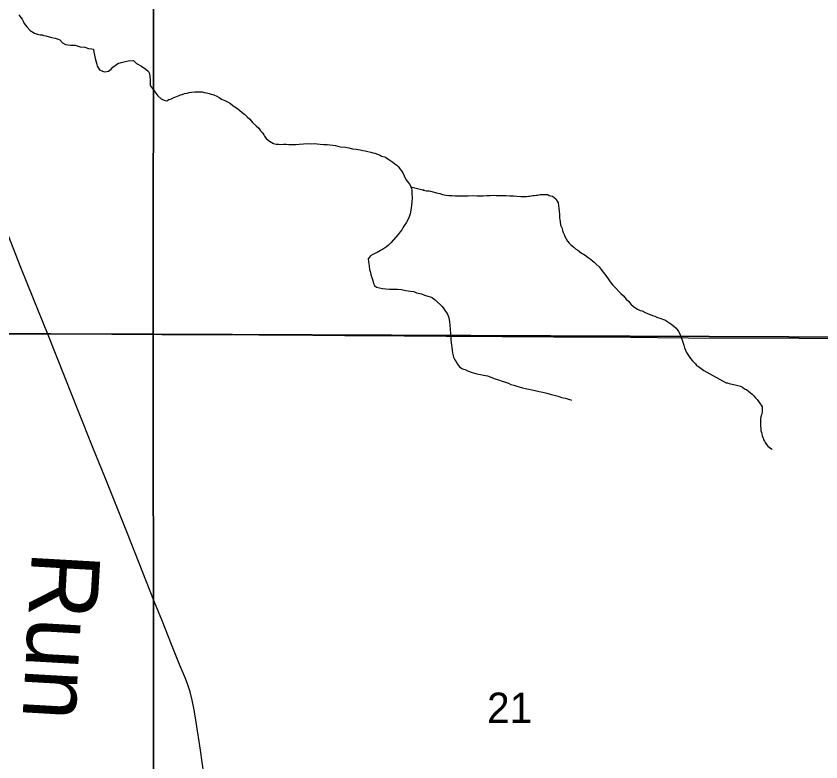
# Model space of a CAD drawing. Extents: x -17 to 88, y -5 to 22.
# Drawn here: x 4.539 to 5.65, y 16.562 to 17.592 of the extents above; entities that cross this region are included whole.
import ezdxf

# ---------------------------------------------------------------- set-up
doc = ezdxf.new("R2010")
doc.units = 0
for name, color, linetype in [('GM_X_County_Road', 7, 'Continuous'), ('GM_X_Minor_River', 7, 'Continuous'), ('GM_X_Minor_River_Text', 7, 'Continuous'), ('GM_X_Section', 7, 'Continuous'), ('GM_X_Section_Text', 7, 'Continuous'), ('GM_X_Township_Road', 7, 'Continuous')]:
    doc.layers.add(name, color=color, linetype=linetype)

msp = doc.modelspace()

# ---------------------------------------------------------------- linework, layer by layer
at = {"layer": 'GM_X_County_Road'}
for points in [[(4.5822, 17.1526), (4.5624, 17.2013), (4.5452, 17.2446), (4.5249, 17.2967), (4.5025, 17.3533), (4.4852, 17.3966), (4.465, 17.4468), (4.4557, 17.4711), (4.4465, 17.4945), (4.4303, 17.5366), (4.4188, 17.5655), (4.4017, 17.6101), (4.3874, 17.6462)], [(4.8002, 16.5279), (4.7931, 16.5777), (4.7874, 16.6165), (4.7846, 16.6337), (4.7819, 16.6471), (4.7789, 16.6586), (4.7758, 16.6681), (4.7725, 16.6769), (4.7644, 16.6964), (4.7531, 16.724), (4.7406, 16.7558), (4.73, 16.7824), (4.6916, 16.8795), (4.6786, 16.9118), (4.661, 16.9556), (4.6456, 16.9937), (4.624, 17.048), (4.6062, 17.0924), (4.5822, 17.1526)]]:
    msp.add_lwpolyline(points, dxfattribs=at)
at = {"layer": 'GM_X_Minor_River'}
for points in [[(4.5423, 17.5938), (4.545, 17.59), (4.5468, 17.5877), (4.5483, 17.5851), (4.5498, 17.582), (4.5532, 17.5771), (4.5581, 17.5721), (4.5638, 17.5686), (4.5683, 17.5671), (4.5718, 17.5663), (4.5744, 17.5663), (4.5763, 17.5655), (4.5797, 17.5647), (4.5873, 17.5628), (4.5926, 17.5616), (4.5968, 17.5604), (4.599, 17.5593), (4.6028, 17.5551), (4.6066, 17.5531), (4.61, 17.5523), (4.6138, 17.5519), (4.6176, 17.5519), (4.6202, 17.5519), (4.6271, 17.5499), (4.6335, 17.5491), (4.6384, 17.5476), (4.643, 17.5468), (4.6456, 17.5464), (4.646, 17.5422), (4.6482, 17.5316), (4.6501, 17.5255), (4.6504, 17.5228), (4.6523, 17.5201), (4.6538, 17.5179), (4.658, 17.5159), (4.6606, 17.5151), (4.664, 17.5155), (4.6663, 17.5159), (4.6697, 17.5189), (4.6724, 17.5215), (4.6755, 17.5238), (4.6789, 17.5268), (4.6835, 17.5279), (4.6892, 17.5293), (4.6934, 17.5301), (4.7006, 17.5308), (4.7047, 17.5266), (4.7119, 17.5231), (4.7176, 17.5189), (4.7214, 17.5158), (4.7229, 17.5128), (4.7236, 17.504), (4.7239, 17.4972), (4.7246, 17.4949), (4.7269, 17.4919), (4.7291, 17.4888), (4.7314, 17.4858), (4.7344, 17.482), (4.7389, 17.4777), (4.7442, 17.4754), (4.7469, 17.475), (4.7496, 17.4769), (4.7534, 17.478), (4.7564, 17.4795)], [(4.7564, 17.4795), (4.7591, 17.4806), (4.7614, 17.4814), (4.7637, 17.4825), (4.7656, 17.4832), (4.7682, 17.484), (4.7713, 17.4851), (4.7747, 17.4858), (4.7777, 17.4866), (4.7808, 17.4869), (4.7857, 17.4873), (4.7956, 17.4876), (4.7986, 17.4868), (4.8016, 17.486), (4.8051, 17.4852), (4.8081, 17.4844), (4.8119, 17.4833), (4.8157, 17.4817), (4.8191, 17.4798), (4.8225, 17.4775), (4.827, 17.4756), (4.8308, 17.4736), (4.8346, 17.4713), (4.8383, 17.4683), (4.8429, 17.4652), (4.847, 17.4621), (4.8508, 17.4591), (4.8546, 17.456), (4.858, 17.4529), (4.8614, 17.4495), (4.8651, 17.4453), (4.8704, 17.4403), (4.8738, 17.4373), (4.8764, 17.4334), (4.8791, 17.4308), (4.8806, 17.4281), (4.8817, 17.4262), (4.884, 17.4231), (4.8866, 17.4205), (4.8885, 17.4193), (4.8942, 17.4162), (4.898, 17.4154), (4.9014, 17.415), (4.9044, 17.4146), (4.9078, 17.415), (4.9116, 17.415), (4.9154, 17.4149), (4.92, 17.4149), (4.9249, 17.4149), (4.9298, 17.4152), (4.9355, 17.4155), (4.9428, 17.4159), (4.9473, 17.4158), (4.9511, 17.4162), (4.9545, 17.4158), (4.9587, 17.4154), (4.9636, 17.4149), (4.9682, 17.4145), (4.98, 17.4133), (4.983, 17.4125), (4.9868, 17.4117), (4.9936, 17.4109), (4.9982, 17.4101), (5.0031, 17.4089), (5.0084, 17.4081), (5.0137, 17.4073), (5.0175, 17.4066), (5.0209, 17.4058), (5.0247, 17.405), (5.0285, 17.4042), (5.0315, 17.4034), (5.0342, 17.4026), (5.038, 17.4015), (5.0406, 17.4003), (5.0436, 17.3988), (5.0474, 17.3976), (5.0505, 17.3961), (5.0535, 17.3941), (5.0565, 17.3922), (5.0591, 17.3903), (5.0618, 17.388), (5.0648, 17.3861), (5.0667, 17.3838), (5.0686, 17.3811), (5.0712, 17.3785), (5.0727, 17.3754), (5.0746, 17.3716), (5.0772, 17.3663), (5.0806, 17.3617), (5.0825, 17.3594), (5.084, 17.356), (5.0847, 17.3541), (5.0851, 17.351), (5.0854, 17.3476), (5.0857, 17.3412), (5.0853, 17.3355), (5.0849, 17.3302), (5.0841, 17.3241), (5.0829, 17.3188), (5.0814, 17.3146), (5.0798, 17.3105)], [(5.084, 17.356), (5.1022, 17.3517), (5.101, 17.3517), (5.1033, 17.3513), (5.1056, 17.3509), (5.1086, 17.3505), (5.1113, 17.3501), (5.1192, 17.3481), (5.1238, 17.3469), (5.1279, 17.3458), (5.1321, 17.3446), (5.1366, 17.3442), (5.1412, 17.3441), (5.1454, 17.3437), (5.1492, 17.3437), (5.1534, 17.3437), (5.1579, 17.344), (5.1632, 17.344), (5.1693, 17.3443), (5.1754, 17.3439), (5.1837, 17.3438), (5.189, 17.3442), (5.1936, 17.3441), (5.1978, 17.3445), (5.202, 17.3444), (5.2061, 17.3444), (5.2107, 17.3444), (5.2156, 17.3443), (5.2206, 17.3439), (5.2259, 17.3439), (5.2304, 17.3435), (5.2361, 17.343), (5.2403, 17.343), (5.2437, 17.343), (5.2464, 17.3433), (5.2483, 17.3433), (5.2502, 17.3437), (5.2525, 17.3441), (5.2547, 17.3444), (5.257, 17.3448), (5.2589, 17.3448), (5.2627, 17.3455), (5.265, 17.3455), (5.2677, 17.3455), (5.2703, 17.3454), (5.2726, 17.3454), (5.2752, 17.3443), (5.2771, 17.3439), (5.2798, 17.3431), (5.2843, 17.3396), (5.2862, 17.3366), (5.2873, 17.3339), (5.288, 17.3305), (5.2884, 17.3256), (5.2888, 17.3233), (5.2887, 17.3214), (5.2891, 17.3195), (5.2891, 17.3176), (5.2891, 17.3157), (5.2894, 17.3134), (5.2898, 17.3104), (5.2902, 17.3081), (5.2909, 17.3032), (5.2928, 17.2986), (5.2935, 17.2959), (5.2946, 17.2929), (5.2957, 17.2902), (5.2968, 17.2876), (5.2983, 17.2845), (5.3006, 17.2811), (5.3029, 17.2784), (5.3047, 17.2765), (5.307, 17.2746), (5.3093, 17.2727), (5.3115, 17.2704), (5.3146, 17.2685), (5.3168, 17.2669), (5.3198, 17.2646), (5.3225, 17.2631), (5.3248, 17.2619), (5.3289, 17.2585), (5.3316, 17.2566), (5.3346, 17.2543), (5.3372, 17.252), (5.3402, 17.2493), (5.344, 17.2455), (5.347, 17.242), (5.3493, 17.2386), (5.3519, 17.2355), (5.3542, 17.2325), (5.3564, 17.229), (5.3594, 17.2249), (5.3624, 17.221), (5.3655, 17.218), (5.3741, 17.2088), (5.3779, 17.2054), (5.3813, 17.2012), (5.385, 17.1977), (5.3881, 17.1943), (5.3915, 17.1908), (5.3949, 17.1885)], [(5.0798, 17.3105), (5.0775, 17.3067), (5.0752, 17.3033), (5.0733, 17.3003), (5.0714, 17.2969), (5.0691, 17.2939), (5.0664, 17.2905), (5.0564, 17.2788), (5.053, 17.2758), (5.0503, 17.2735), (5.0477, 17.2716), (5.0446, 17.2698), (5.0419, 17.2683), (5.0397, 17.2668), (5.0374, 17.2656), (5.0343, 17.2641), (5.0313, 17.2626), (5.0282, 17.2608), (5.0267, 17.2589), (5.0251, 17.2566), (5.0255, 17.2532), (5.0259, 17.2505), (5.0262, 17.2468), (5.0269, 17.2422), (5.0281, 17.238), (5.0288, 17.2346), (5.0299, 17.2308), (5.0314, 17.227), (5.0325, 17.2228), (5.0336, 17.2198), (5.0363, 17.2175), (5.045, 17.2159), (5.0492, 17.2155), (5.0545, 17.215), (5.0655, 17.2146), (5.0708, 17.2142), (5.0769, 17.213), (5.0833, 17.2122), (5.0879, 17.2114), (5.0916, 17.2098), (5.0985, 17.2083), (5.103, 17.2067), (5.1072, 17.2052), (5.1113, 17.204), (5.114, 17.2028), (5.1159, 17.2013), (5.1181, 17.1994), (5.1272, 17.191), (5.1294, 17.1875), (5.1325, 17.1837), (5.134, 17.181), (5.1355, 17.178), (5.1362, 17.1753), (5.1369, 17.1731), (5.1373, 17.1696), (5.138, 17.1651), (5.1384, 17.1594), (5.1387, 17.1533), (5.139, 17.1488), (5.1394, 17.145), (5.1397, 17.1408), (5.1401, 17.1374), (5.1405, 17.1343), (5.1408, 17.1309), (5.1415, 17.1263), (5.143, 17.121), (5.1445, 17.1172), (5.1464, 17.1142), (5.1486, 17.1111), (5.1513, 17.1077), (5.1543, 17.1054), (5.1566, 17.1042), (5.1592, 17.1038), (5.1622, 17.1019), (5.1687, 17.0996), (5.1751, 17.098), (5.1804, 17.0968), (5.1842, 17.096), (5.1899, 17.0952), (5.1937, 17.0937), (5.199, 17.0914), (5.2051, 17.0894), (5.21, 17.0875), (5.2145, 17.0863), (5.2187, 17.0848), (5.2221, 17.0832), (5.2263, 17.0821), (5.2304, 17.0809), (5.2338, 17.0797), (5.2384, 17.0786), (5.2422, 17.0774), (5.2558, 17.0746), (5.2611, 17.0735), (5.2664, 17.0723), (5.2718, 17.0711), (5.2763, 17.0699), (5.282, 17.0684), (5.2873, 17.0668), (5.2922, 17.0652), (5.2971, 17.0641), (5.3002, 17.0633)], [(5.3949, 17.1885), (5.3971, 17.1874), (5.399, 17.1862), (5.4009, 17.1855), (5.4036, 17.1847), (5.4077, 17.1827), (5.4111, 17.1812), (5.4145, 17.18), (5.4179, 17.1785), (5.421, 17.1773), (5.4248, 17.1758), (5.4278, 17.1746), (5.4308, 17.1738), (5.4331, 17.1731), (5.435, 17.1723), (5.4376, 17.1708), (5.4403, 17.1688), (5.4433, 17.1669), (5.4456, 17.165), (5.4475, 17.1638), (5.4505, 17.1608), (5.452, 17.1589), (5.4535, 17.1562), (5.4554, 17.1532), (5.4568, 17.1494), (5.4583, 17.1459), (5.4598, 17.1414), (5.4609, 17.1376), (5.462, 17.1338), (5.4632, 17.1303), (5.465, 17.1273), (5.4665, 17.1246), (5.4684, 17.1219), (5.4703, 17.1189), (5.4729, 17.1158), (5.4756, 17.1135), (5.4771, 17.1116), (5.4786, 17.1094), (5.4812, 17.1078), (5.4831, 17.1067), (5.4888, 17.1024), (5.4968, 17.0978)], [(5.4968, 17.0978), (5.5195, 17.0856), (5.5214, 17.0852), (5.5237, 17.0844), (5.5256, 17.084), (5.5278, 17.0836), (5.5297, 17.0832), (5.532, 17.0824), (5.5396, 17.0807), (5.5422, 17.0795), (5.5448, 17.0772), (5.5482, 17.0756), (5.5505, 17.0737), (5.5531, 17.0717), (5.5553, 17.0698), (5.558, 17.0674), (5.5602, 17.0647), (5.5624, 17.0624), (5.5646, 17.059), (5.5665, 17.0563), (5.568, 17.0543), (5.5691, 17.0524), (5.5694, 17.0505), (5.5694, 17.0475), (5.5693, 17.0448), (5.5685, 17.041), (5.5677, 17.0384), (5.5672, 17.0354), (5.5672, 17.0327), (5.5671, 17.0297), (5.5671, 17.0255), (5.5674, 17.0225), (5.5677, 17.0194), (5.5684, 17.0167), (5.5688, 17.0148), (5.5695, 17.0122), (5.5706, 17.0091), (5.5713, 17.0072), (5.5724, 17.0049), (5.5735, 17.003), (5.5753, 17.0003), (5.5772, 16.998), (5.5791, 16.9964), (5.5821, 16.9941), (5.5832, 16.9933)], [(5.3002, 17.0633), (5.3032, 17.0625), (5.3051, 17.0617), (5.3059, 17.0613)]]:
    msp.add_lwpolyline(points, dxfattribs=at)
at = {"layer": 'GM_X_Section'}
for points in [[(3.7341, 18.1579), (4.7287, 18.1546), (4.728, 17.1525), (3.7342, 17.1557)], [(5.7233, 18.1499), (5.716, 17.1483), (4.728, 17.1525), (4.7287, 18.1546)], [(3.7342, 17.1557), (4.728, 17.1525), (4.7288, 16.1466), (3.7278, 16.1476)], [(4.728, 17.1525), (5.716, 17.1483), (5.7141, 16.1466), (4.7288, 16.1466)]]:
    msp.add_lwpolyline(points, close=True, dxfattribs=at)
at = {"layer": 'GM_X_Township_Road'}
for points in [[(3.4852, 17.1552), (3.5884, 17.1564), (3.6356, 17.1568), (3.6996, 17.157), (3.8475, 17.1571), (3.8736, 17.157), (3.9823, 17.1566), (4.0165, 17.1567), (4.0401, 17.1568), (4.0773, 17.1568), (4.1406, 17.1568), (4.2071, 17.1562), (4.2879, 17.1557), (4.3487, 17.155), (4.45, 17.1542), (4.5227, 17.1533), (4.5822, 17.1526)], [(4.5822, 17.1526), (4.6019, 17.153), (4.7399, 17.1524), (4.7939, 17.152), (4.8741, 17.1516), (4.9486, 17.1512), (4.9928, 17.1507), (5.0748, 17.1505), (5.1326, 17.1501), (5.2102, 17.1493), (5.2811, 17.1488), (5.3879, 17.1484), (5.4246, 17.1482), (5.4675, 17.1478), (5.6203, 17.1469), (5.68, 17.1465), (5.7334, 17.1464), (5.7974, 17.1463), (5.8894, 17.1459), (5.9155, 17.1458), (5.9405, 17.1462)]]:
    msp.add_lwpolyline(points, dxfattribs=at)

# ---------------------------------------------------------------- texts
at = {"layer": 'GM_X_Minor_River_Text'}
msp.add_text('Run', height=0.09472, rotation=266.7174, dxfattribs=at).set_placement((4.5607, 16.8539))
at = {"layer": 'GM_X_Section_Text'}
msp.add_text('21', height=0.04186, rotation=0, dxfattribs=at).set_placement((5.1893, 16.6155))

doc.saveas('drawing.dxf')
